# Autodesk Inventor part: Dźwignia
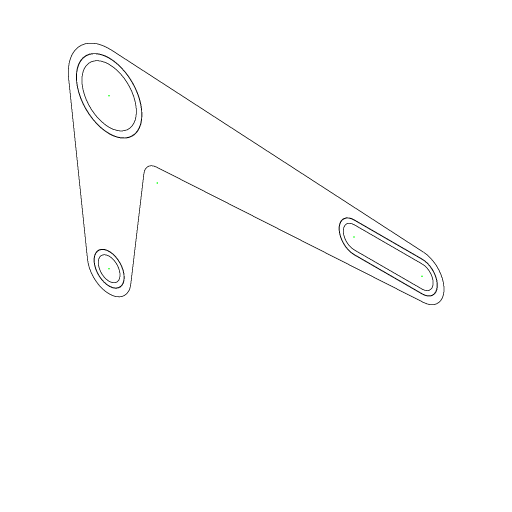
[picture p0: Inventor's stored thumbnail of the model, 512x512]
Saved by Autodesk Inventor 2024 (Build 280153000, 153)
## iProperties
Company: ATC
Created: 2023-03
Part Number: Dźwignia
Material: Ogólny
Document SubType Name: Modeling
Designer: Andrzej Jaskulski
Density: 1 g/cm^3
Appearance: Domyślna
Checked By: A.J.
Engr Approved By: Andrzej Jaskulski
Mfg Approved By: Andrzej Jaskulski
Authority: A.J.
Author: Andrzej Jaskulski
Title: A.J.: Kurs R2024-MEP
Revision Number: 1/24
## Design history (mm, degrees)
sketch "Szkic1"
  geometry: L1 (58.913, 179.896)-(173.487, 172.909); L2 (50.065, 108.906)-(43.122, 163.015); L3 (70.772, 146.605)-(65.935, 108.906); L4 (173.487, 156.939)-(75.427, 150.959); L5 (148, 170.399)-(173, 170.399); L6 (148, 170.487)-(173, 170.487); L7 (173, 159.449)-(148, 159.449); L8 (173, 159.362)-(148, 159.362); L9 (148, 168.924)-(173, 168.924); L10 (173, 160.924)-(148, 160.924); C1 r 12.063 at (58, 164.924); C2 r 11.975 at (58, 164.924); C3 r 5.563 at (58, 109.924); C4 r 5.475 at (58, 109.924); C5 r 10 at (58, 164.924); C6 r 4 at (58, 109.924); A1 r 15 centre (58, 164.924) between (58.913, 179.896) and (43.122, 163.015); A2 r 8 centre (58, 109.924) between (50.065, 108.906) and (65.935, 108.906); A3 r 5 centre (75.731, 145.968) between (75.427, 150.959) and (70.772, 146.605); A4 r 8 centre (173, 164.924) between (173.487, 156.939) and (173.487, 172.909); A5 r 5.475 centre (148, 164.924) between (148, 170.399) and (148, 159.449); A6 r 5.563 centre (148, 164.924) between (148, 170.487) and (148, 159.362); A7 r 5.475 centre (173, 164.924) between (173, 159.449) and (173, 170.399); A8 r 5.563 centre (173, 164.924) between (173, 159.362) and (173, 170.487); A9 r 4 centre (173, 164.924) between (173, 160.924) and (173, 168.924); A10 r 4 centre (148, 164.924) between (148, 168.924) and (148, 160.924)
  constraints: 20 end point, 20 point on circle, 17 tangent, 16 centre point, 7 equal radius, 5 parallel
